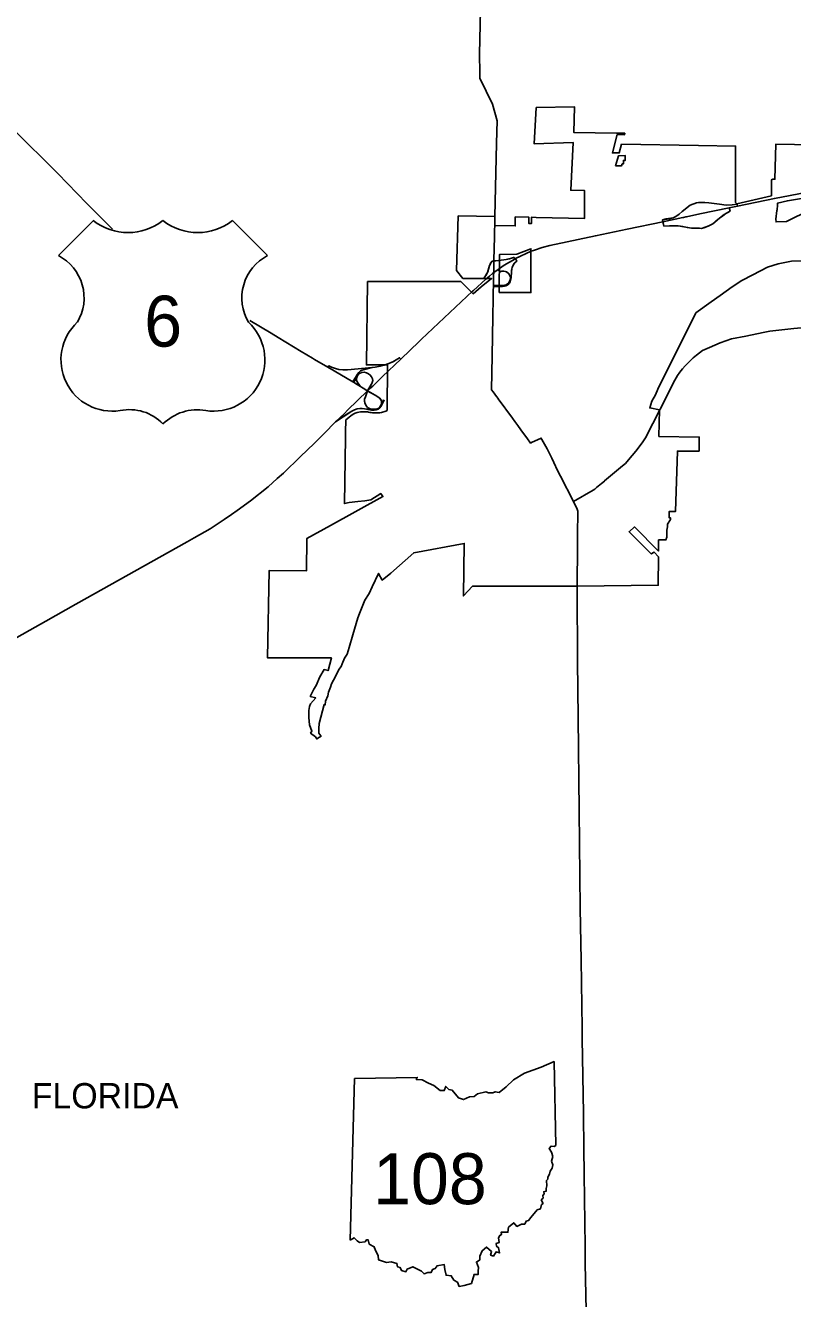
# Model space of a CAD drawing. Extents: x -62 to 810, y 0 to 440.
# Drawn here: x 239.8 to 317.5, y 199.3 to 328.2 of the extents above; entities that cross this region are included whole.
import ezdxf

# ---------------------------------------------------------------- set-up
doc = ezdxf.new("R2010")
doc.units = 0
for name, color, linetype in [('Default', 7, 'Continuous'), ('DV_X_Corp_Line', 7, 'Continuous'), ('GM_X_Corporation_Text', 7, 'Continuous'), ('GM_X_State_Route', 7, 'Continuous'), ('PV_P_Text', 7, 'Continuous')]:
    doc.layers.add(name, color=color, linetype=linetype)

msp = doc.modelspace()

# ---------------------------------------------------------------- linework, layer by layer
at = {"layer": 'Default'}
for points in [[(311.94, 309.96), (311.9, 310.13), (311.4, 310.09), (310.78, 310.06), (310.11, 310.14), (309.04, 310.29), (308.25, 310.33), (307.78, 310.28), (307.16, 310.03), (306.34, 309.41), (306.03, 309.14), (305.69, 308.89), (305.44, 308.76), (304.71, 308.66), (304.36, 308.55)], [(304.36, 308.55), (304.49, 307.92), (305.05, 307.96), (305.94, 307.94), (307.29, 307.73), (308.28, 307.69), (309.03, 307.94), (309.45, 308.17), (310.13, 308.72), (310.6, 309.11), (311.19, 309.43), (311.11, 309.78)], [(286.47, 302.54), (286.3, 302.73), (286.44, 302.93), (286.62, 303.23), (286.83, 303.94), (286.98, 304.24), (287.11, 304.36), (287.46, 304.41), (288, 304.49), (288.51, 304.55), (289.05, 304.67), (289.3, 304.75), (289.39, 304.59)], [(289.47, 304.64), (289.61, 304.39), (289.43, 304.23), (289.26, 304.03), (289.13, 303.74), (289.08, 303.59), (289.04, 303.26), (289.02, 302.72), (288.97, 302.41), (288.93, 302.28), (288.75, 302.04), (288.48, 301.87), (288.13, 301.82), (287.22, 301.82)], [(287.22, 301.92), (288.13, 301.92), (288.52, 301.97), (288.75, 302.14), (288.9, 302.39), (288.94, 302.67), (288.93, 302.81), (288.85, 302.98), (288.78, 303.1), (288.56, 303.28), (288.26, 303.37), (288.09, 303.36), (287.86, 303.29), (287.69, 303.53)], [(270.46, 293.64), (270.55, 293.77), (270.84, 293.63), (271.23, 293.49), (271.57, 293.41), (271.96, 293.36), (272.43, 293.38), (274.94, 293.61), (275.25, 293.64), (275.76, 293.73), (276.17, 293.84), (276.63, 294), (277.11, 294.22), (277.37, 294.37), (277.72, 294.6), (277.86, 294.45)], [(272.99, 292.16), (273.45, 292.94), (273.59, 293.11), (273.78, 293.26), (274.02, 293.37), (274.94, 293.61)], [(273.06, 292.11), (273.48, 292.82), (273.58, 292.95), (273.72, 293.04), (273.91, 293.11), (274.14, 293.12), (274.37, 293.07), (274.56, 292.97), (274.75, 292.84), (274.89, 292.66), (274.98, 292.47), (275, 292.28), (274.96, 292.09), (274.89, 291.93), (274.47, 291.23)], [(273.73, 291.71), (273.42, 292.15), (273.37, 292.31), (273.36, 292.48), (273.41, 292.68), (273.48, 292.82)], [(276.15, 290.33), (276.12, 290.23), (275.81, 289.67), (275.71, 289.53), (275.56, 289.4), (275.35, 289.31), (275.12, 289.27), (274.87, 289.29), (274.53, 289.35), (274.16, 289.42), (273.94, 289.44), (273.69, 289.44), (273.42, 289.41), (273.15, 289.33), (272.87, 289.19), (272.39, 288.87), (271.24, 288.1)], [(275.85, 289.81), (275.72, 289.63), (275.65, 289.55), (275.55, 289.47), (275.44, 289.42), (275.19, 289.37), (274.98, 289.38), (274.75, 289.42), (274.48, 289.57), (274.37, 289.69), (274.29, 289.8), (274.19, 290.04), (274.17, 290.27), (274.18, 290.39), (274.26, 290.65), (274.47, 291.23)], [(274.47, 291.23), (275.24, 290.81), (275.71, 290.49), (275.84, 290.3), (275.88, 290.13), (275.88, 289.96), (275.85, 289.81), (276.07, 290.25), (276.1, 290.34)]]:
    msp.add_lwpolyline(points, dxfattribs=at)
at = {"layer": 'DV_X_Corp_Line'}
for points in [[(318.46, 304.41), (317.4, 304.36), (316.05, 304.12), (314.97, 303.76), (313.49, 303), (312.37, 302.42), (311.4, 301.76), (310.2, 300.9), (309.27, 300.24), (307.72, 299.14), (305.01, 293.72), (304.06, 291.78), (303.89, 291.4), (303.64, 290.85), (303.28, 290.2), (303.05, 289.51), (304.03, 289.33), (303.99, 286.62), (308.07, 286.56), (308.05, 285.15), (305.86, 285.15), (305.65, 279.02), (305.03, 279.03), (305.03, 278.38), (305.17, 278.38), (305.17, 278.23), (304.87, 277.74), (304.86, 277.46), (304.78, 277.13), (304.77, 276.42), (304.69, 276.14), (303.95, 276.14), (303.94, 275.01), (301.5, 277.46), (300.97, 276.98), (303.21, 274.73), (303.49, 274.91), (303.93, 274.44), (303.92, 271.55), (295.7, 271.45), (285.11, 271.46), (284.19, 270.48), (284.27, 275.79), (279.16, 274.84), (276.84, 272.79), (275.96, 272.08), (275.59, 272.75), (274.96, 271.39), (274.65, 270.72), (274.19, 270.03), (273.67, 268.69), (273.48, 268.24), (273, 266.54), (272.6, 265.24), (272.42, 264.56), (272.14, 264.18), (271.89, 263.61), (271.82, 263.33), (271.57, 263.03), (271.23, 262.33), (270.84, 261.58), (270.74, 261.24), (270.52, 260.72), (270.45, 260.35), (270.21, 259.81), (270.19, 259.44), (270.09, 259.47), (269.58, 257.57), (269.53, 257.04), (269.56, 256.59), (269.75, 256.31), (269.77, 256.27), (269.61, 256.17), (269.33, 255.99), (269.19, 256.21), (268.71, 256.59), (268.85, 256.78), (268.59, 257.43), (268.52, 258.15), (268.54, 258.86), (268.6, 259.27), (268.71, 259.56), (269.23, 260.14), (268.68, 260.3), (269.04, 261.04), (269.28, 261.42), (269.64, 262.27), (270.08, 263.02), (270.48, 262.92), (270.81, 264.19), (264.34, 264.21), (264.51, 273.04), (268.31, 273.03), (268.33, 276.29), (270.73, 277.62), (276.03, 280.53), (275.82, 280.84), (274.82, 280.2), (274.2, 280.1), (273.51, 280.04), (272.6, 279.93), (272.14, 279.83), (272.23, 286.47), (272.24, 287.4), (272.28, 287.96), (272.29, 288.22), (272.29, 288.29), (272.41, 288.41), (272.62, 288.58), (272.78, 288.72), (273.01, 288.88), (273.22, 288.97), (273.42, 289.05), (273.76, 289.11), (273.84, 289.12), (274.03, 289.13), (274.22, 289.12), (274.29, 289.11), (274.48, 289.1), (274.57, 289.08), (274.71, 289.06), (274.84, 289.04), (274.99, 289.03), (275.13, 289.01), (275.22, 289.01), (275.33, 289.01), (275.52, 289.01), (275.72, 289.03), (275.9, 289.04), (276.34, 289.19), (276.46, 289.26), (276.49, 293.87), (274.36, 293.87), (274.48, 302.3), (283.92, 302.31), (285.17, 301.07), (285.99, 301.79), (287.03, 302.61), (284.14, 302.62), (283.49, 303.42), (283.67, 308.96), (287.38, 308.88), (287.36, 307.98), (289.44, 307.94), (289.44, 308.85), (290.81, 308.83), (290.8, 308.19), (291.08, 308.18), (291.08, 308.82), (291.57, 308.81), (296.44, 308.69), (296.44, 311.53), (295.05, 311.55), (295.31, 316.39), (291.36, 316.25), (291.56, 319.93), (295.45, 320), (295.36, 317.41), (299.68, 317.33), (300.53, 317.32), (300.5, 317.18), (299.76, 317.19), (299.27, 315.34), (299.97, 315.33), (300.21, 316.22), (307.98, 316.09), (311.75, 316.02), (311.75, 312.41), (311.75, 311.94), (311.75, 310.31), (311.89, 310.18), (315.37, 310.99), (315.37, 311.53), (315.39, 312.62), (315.53, 312.67), (315.73, 312.67), (315.82, 316.22), (323.35, 316.08)], [(319.65, 310.93), (316.99, 310.49), (316.01, 310.26), (316.01, 310.05), (315.97, 309.56), (315.93, 309.49), (315.82, 308.63), (315.85, 308.34), (316.9, 308.39), (321.62, 310.73)]]:
    msp.add_lwpolyline(points, dxfattribs=at)
for points in [[(299.59, 314.02), (300.21, 314.03), (300.27, 314.23), (300.39, 314.23), (300.39, 314.58), (300.58, 314.58), (300.58, 315.06), (299.88, 315.04)], [(287.81, 301.19), (291.03, 301.19), (291.03, 305.63), (289.58, 305.07), (287.83, 305.04)]]:
    msp.add_lwpolyline(points, close=True, dxfattribs=at)
at = {"layer": 'GM_X_State_Route'}
for points in [[(285.82, 325.35), (286.13, 338.85), (286.31, 346.44), (286.48, 354.03), (286.82, 369.18), (287.34, 391.58)], [(198.53, 333.88), (207.22, 331.68), (212.44, 330.67), (218.02, 329.23), (220.04, 328.78), (225.63, 327.52), (227.85, 327.08), (228.67, 326.87), (229.44, 326.61), (229.96, 326.29), (230.45, 325.9), (231.43, 324.88), (234.84, 321.46), (239.2, 317.13), (242.46, 313.89), (243.11, 313.25), (246.06, 310.2), (246.72, 309.53), (248.65, 307.6)], [(285.84, 323.71), (285.84, 323.86), (285.81, 324.92), (285.82, 325.35)], [(287.54, 316.31), (287.59, 318.6), (287.13, 320.26), (285.86, 322.91), (285.84, 323.71)], [(287.41, 310.36), (287.54, 316.31)], [(306.78, 308.87), (308.12, 309.15), (311.11, 309.78), (311.94, 309.96), (315.68, 310.73), (318.86, 311.33), (321.03, 311.55), (323.21, 311.68), (323.38, 311.68)], [(287.38, 308.87), (287.38, 308.88), (287.41, 310.36)], [(308.13, 310.33), (308, 310.33), (307.78, 310.28), (307.16, 310.03), (306.8, 309.78), (306.34, 309.41), (306.03, 309.14), (305.69, 308.89), (305.44, 308.76), (305.06, 308.65), (304.36, 308.55), (304.39, 308.37)], [(311.11, 309.78), (311.19, 309.43), (310.75, 309.21), (310.45, 308.98), (310.13, 308.72), (309.74, 308.42), (309.45, 308.17), (309.03, 307.94), (308.64, 307.79), (308.28, 307.69), (307.29, 307.73), (306.86, 307.79), (306.41, 307.87), (305.94, 307.94), (305.53, 307.96), (305.05, 307.96), (304.49, 307.92), (304.39, 308.37)], [(311.94, 309.96), (311.9, 310.13), (311.4, 310.09), (310.78, 310.06), (310.11, 310.14), (309.58, 310.22), (309.04, 310.29), (308.65, 310.31), (308.25, 310.33), (308.13, 310.33)], [(287.34, 307.38), (287.36, 308.12)], [(287.36, 308.12), (287.38, 308.87)], [(291.3, 305.46), (291.38, 305.49), (292.17, 305.77), (292.95, 305.97), (297.56, 306.94), (300.76, 307.61), (304.39, 308.37), (306.42, 308.8), (306.48, 308.81)], [(304.39, 308.37), (304.49, 307.92), (305.05, 307.96), (305.53, 307.96), (305.94, 307.94), (306.41, 307.87), (306.86, 307.79), (307.29, 307.73), (308.02, 307.7), (308.1, 307.7)], [(306.48, 308.81), (306.72, 308.86), (306.78, 308.87)], [(287.33, 306.78), (287.34, 307.38)], [(287.27, 304.4), (287.3, 305.74)], [(287.3, 305.74), (287.33, 306.78)], [(287.27, 304.4), (287.17, 304.38), (287.11, 304.36), (287.04, 304.3), (286.98, 304.24), (286.93, 304.17), (286.89, 304.08), (286.83, 303.94), (286.73, 303.56), (286.69, 303.38), (286.62, 303.23), (286.54, 303.08), (286.44, 302.93), (286.36, 302.8), (286.3, 302.73), (286.47, 302.54)], [(287.22, 301.82), (287.39, 301.81), (287.79, 301.82), (288.13, 301.82), (288.33, 301.83), (288.48, 301.87), (288.63, 301.95), (288.75, 302.04), (288.86, 302.16), (288.93, 302.28), (288.97, 302.41), (289, 302.55), (289.02, 302.72), (289.04, 303.26), (289.05, 303.42), (289.08, 303.59), (289.13, 303.74), (289.18, 303.89), (289.26, 304.03), (289.34, 304.13), (289.43, 304.23), (289.53, 304.33), (289.61, 304.39), (289.47, 304.64)], [(287.25, 303.22), (287.27, 304.4)], [(289.39, 304.59), (289.3, 304.75), (289.26, 304.73), (289.05, 304.67), (288.84, 304.62), (288.51, 304.55), (287.77, 304.43), (287.46, 304.41), (287.27, 304.4)], [(287.83, 303.63), (288.31, 303.97), (289.39, 304.59), (289.47, 304.64), (291.04, 305.37), (291.3, 305.46)], [(285.12, 301.33), (285.2, 301.4), (286.47, 302.54), (286.84, 302.86), (287.12, 303.11)], [(287.12, 303.11), (287.13, 303.12), (287.25, 303.22)], [(287.69, 303.53), (287.86, 303.29), (287.9, 303.31), (288.09, 303.36), (288.26, 303.37), (288.42, 303.34), (288.56, 303.28), (288.69, 303.2), (288.78, 303.1), (288.85, 302.98), (288.93, 302.81), (288.94, 302.67), (288.94, 302.55), (288.9, 302.39), (288.85, 302.28), (288.75, 302.14), (288.64, 302.05), (288.52, 301.97), (288.38, 301.93), (288.25, 301.91), (288.04, 301.9), (287.41, 301.91), (287.22, 301.92)], [(287.24, 302.9), (287.25, 303.22)], [(287.25, 303.22), (287.69, 303.53), (287.83, 303.63)], [(287.21, 301.36), (287.22, 301.82), (287.22, 301.92), (287.24, 302.9)], [(279.71, 296.25), (279.95, 296.48), (285.12, 301.33)], [(287.2, 300.29), (287.2, 300.32), (287.21, 300.9)], [(287.21, 300.9), (287.21, 300.93), (287.21, 301.36)], [(287.17, 299.07), (287.2, 300.29)], [(262.56, 298.35), (264.7, 297.07), (265.43, 296.63), (267.75, 295.24), (268.91, 294.55), (269, 294.5)], [(287.1, 294.79), (287.17, 298.76)], [(287.17, 298.76), (287.17, 298.79), (287.17, 299.07)], [(315.23, 297.3), (317.65, 297.55), (323.83, 298.09), (328.62, 298.4), (330.19, 298.59)], [(306.64, 293.78), (306.67, 293.81), (307.1, 294.26), (307.44, 294.58), (307.78, 294.86), (308.4, 295.32), (309.1, 295.62), (310.19, 296.12), (311.34, 296.5), (312.77, 296.79)], [(312.77, 296.79), (312.78, 296.79), (314.55, 297.16)], [(314.55, 297.16), (315.23, 297.3)], [(275.99, 292.68), (276, 292.69), (277.86, 294.45), (279.71, 296.25)], [(269, 294.5), (269.12, 294.42), (270.46, 293.64)], [(277.86, 294.45), (277.72, 294.6), (277.37, 294.37), (277.03, 294.19), (276.63, 294), (276.17, 293.84), (275.76, 293.73), (275.25, 293.64), (274.94, 293.61), (274.23, 293.53), (272.43, 293.38), (271.96, 293.36), (271.57, 293.41), (271.23, 293.49), (270.84, 293.63), (270.55, 293.77), (270.46, 293.64)], [(287.71, 290.42), (287.69, 290.45), (287.54, 290.66), (287.19, 291.14), (287.04, 291.34), (287.1, 294.79)], [(270.46, 293.64), (271.11, 293.26), (272.99, 292.16), (273.06, 292.11), (273.42, 291.9), (274.21, 291.4)], [(274.94, 293.61), (274.24, 293.43), (274.02, 293.37), (273.78, 293.26), (273.59, 293.11), (273.45, 292.94), (273.04, 292.25), (272.99, 292.16)], [(273.06, 292.11), (273.12, 292.2), (273.48, 292.82), (273.41, 292.68)], [(273.73, 291.71), (273.5, 292.03), (273.42, 292.15), (273.37, 292.31), (273.36, 292.48), (273.41, 292.68), (273.48, 292.82), (273.58, 292.95), (273.72, 293.04), (273.91, 293.11), (274.14, 293.12), (274.37, 293.07), (274.56, 292.97), (274.75, 292.84), (274.89, 292.66), (274.98, 292.47), (275, 292.28), (274.96, 292.09), (274.89, 291.93), (274.86, 291.88), (274.47, 291.23)], [(274.68, 291.43), (275, 291.73), (275.99, 292.68)], [(304.08, 289.33), (304.1, 289.39), (305.6, 292.32), (305.88, 292.8), (306.09, 293.14), (306.36, 293.48), (306.64, 293.78)], [(274.21, 291.4), (274.34, 291.32)], [(274.58, 291.33), (274.68, 291.43)], [(271.24, 288.1), (272.67, 289.06), (272.87, 289.19), (273.15, 289.33), (273.42, 289.41), (273.69, 289.44), (273.94, 289.44), (274.16, 289.42), (274.43, 289.37), (274.87, 289.29), (275.12, 289.27), (275.35, 289.31), (275.56, 289.4), (275.71, 289.53), (275.81, 289.67), (276.12, 290.23), (276.15, 290.33)], [(272.13, 288.96), (272.46, 289.28), (274.47, 291.23)], [(275.78, 290.41), (275.84, 290.3), (275.88, 290.13), (275.88, 289.96), (275.85, 289.81), (275.72, 289.63), (275.65, 289.55), (275.55, 289.47), (275.44, 289.42), (275.19, 289.37), (274.98, 289.38), (274.75, 289.42), (274.61, 289.49), (274.48, 289.57), (274.37, 289.69), (274.29, 289.8), (274.22, 289.96), (274.19, 290.04), (274.18, 290.15), (274.17, 290.27), (274.18, 290.39), (274.26, 290.65), (274.37, 290.94)], [(274.34, 291.32), (274.47, 291.23), (274.74, 291.08)], [(274.37, 290.94), (274.47, 291.23)], [(274.47, 291.23), (274.58, 291.33)], [(274.74, 291.08), (275.24, 290.81), (275.71, 290.49), (275.77, 290.41), (275.78, 290.41)], [(276.1, 290.34), (276.07, 290.25), (275.91, 289.95), (275.85, 289.81)], [(290.6, 286.48), (290.58, 286.51), (290.01, 287.29), (289.68, 287.74), (289.39, 288.13), (289.14, 288.48), (287.71, 290.42)], [(203.42, 246.07), (217.26, 254.07), (234.38, 263.69), (241.91, 267.93), (244.92, 269.63), (256.21, 275.94), (256.92, 276.34), (258.55, 277.28), (259.95, 278.2), (260.7, 278.72), (261.26, 279.12), (262.61, 280.12), (264.4, 281.53), (265.33, 282.35), (265.96, 282.89), (267.7, 284.59), (269.07, 285.92), (270.07, 286.92), (271.24, 288.1), (272.13, 288.96)], [(298.48, 282.12), (300.3, 283.64), (300.59, 283.88), (300.9, 284.25), (301.66, 285.14), (302.28, 285.99), (302.68, 286.58), (302.7, 286.63), (304.04, 289.25), (304.08, 289.33)], [(291.09, 286), (291.06, 285.99), (290.99, 285.95), (290.6, 286.48)], [(292.14, 286.32), (292.11, 286.36), (292.06, 286.45), (291.09, 286)], [(293.33, 283.98), (293.15, 284.41), (292.68, 285.38), (292.14, 286.32)], [(294.02, 282.61), (293.72, 283.19), (293.33, 283.98)], [(295.33, 280.02), (294.02, 282.61)], [(295.33, 280.02), (297.31, 281.19), (297.48, 281.3), (297.67, 281.45)], [(297.67, 281.45), (298.18, 281.87), (298.47, 282.11), (298.48, 282.12)], [(295.73, 274.48), (295.73, 274.94), (295.73, 275.38), (295.74, 276.09), (295.75, 276.78), (295.75, 277.27), (295.76, 278.42), (295.77, 278.95), (295.76, 279.03), (295.76, 279.05), (295.7, 279.26), (295.33, 280.02)], [(295.7, 271.45), (295.71, 272.54), (295.73, 274.45), (295.73, 274.48)], [(295.7, 271.15), (295.7, 271.45)], [(296.33, 217.94), (296.33, 218.09), (296.22, 225.62), (296.21, 226.7), (296.1, 233.6), (296.02, 238.82), (295.9, 248.75), (295.81, 258.14), (295.74, 263.88), (295.7, 271.15)], [(296.73, 185.88), (296.73, 187.78), (296.61, 198.1), (296.52, 202.86), (296.5, 204.59), (296.42, 211.89), (296.39, 214.54), (296.33, 217.94), (296.33, 217.94)]]:
    msp.add_lwpolyline(points, dxfattribs=at)
at = {"layer": 'PV_P_Text'}
for p, q in [((246.71, 308.48), (243.17, 304.94)), ((264.35, 304.94), (260.8, 308.48)), ((272.7, 205.23), (273.16, 221.6)), ((272.7, 205.23), (273.16, 221.6))]:
    msp.add_line(p, q, dxfattribs=at)
for points in [[(273.16, 221.6), (279.51, 221.71), (279.41, 221.51), (280.01, 221.47), (280.65, 221.12), (281.18, 220.9), (281.84, 220.38), (282.24, 220.38), (282.4, 220.81), (282.71, 220.48), (283.06, 220.42), (283.68, 219.64), (284.19, 219.47), (284.81, 219.74), (285.26, 219.78), (285.6, 220.05), (286.47, 220.27), (286.71, 220.14), (287.17, 220.17), (287.41, 220.27), (287.81, 220.18), (288.52, 220.77), (289.25, 221.47), (290.37, 222.14), (292.05, 222.76), (293.37, 223.32), (293.56, 214.83)], [(273.16, 221.6), (279.51, 221.71), (279.41, 221.51), (280.01, 221.47), (280.65, 221.12), (281.18, 220.9), (281.84, 220.38), (282.24, 220.38), (282.4, 220.81), (282.71, 220.48), (283.06, 220.42), (283.68, 219.64), (284.19, 219.47), (284.81, 219.74), (285.26, 219.78), (285.6, 220.05), (286.47, 220.27), (286.71, 220.14), (287.17, 220.17), (287.41, 220.27), (287.81, 220.18), (288.52, 220.77), (289.25, 221.47), (290.37, 222.14), (292.05, 222.76), (293.37, 223.32), (293.56, 214.83)], [(293.56, 214.83), (293.37, 214.71), (293.06, 214.76), (292.86, 214.53), (293.11, 214.13), (293.23, 213.71), (293.12, 213.25), (293.23, 212.86), (293.16, 212.54), (292.97, 212.23), (292.9, 211.92), (292.74, 211.6), (292.75, 211.42), (292.6, 211.28), (292.62, 210.75), (292.55, 210.46), (292.57, 210.2), (292.32, 210.14), (292.38, 209.93), (292.22, 209.76), (292.25, 209.49), (292.07, 209.31), (292.25, 208.95), (292.11, 208.84), (291.99, 208.4), (291.67, 208.32), (291.02, 207.52), (290.79, 207.22), (290.54, 207.15), (290.4, 206.84), (290.08, 206.84), (289.6, 206.63), (289.29, 206.99), (288.75, 206.55), (288.69, 206.04), (288.01, 206.06), (288.03, 205.8), (287.88, 205.72), (287.74, 205.47), (287.82, 205.01), (287.5, 204.89), (287.54, 204.62), (287.75, 204.46), (287.84, 203.95), (287.5, 204.05), (287.22, 203.62), (286.93, 203.72), (287.03, 204.09), (286.54, 204.53), (286.09, 204.17), (285.85, 203.61), (285.84, 203.24), (285.5, 203.01), (285.72, 202.48), (285.68, 202.11), (285.69, 201.76), (285.26, 201.77), (285, 200.83)], [(293.56, 214.83), (293.37, 214.71), (293.06, 214.76), (292.86, 214.53), (293.11, 214.13), (293.23, 213.71), (293.12, 213.25), (293.23, 212.86), (293.16, 212.54), (292.97, 212.23), (292.9, 211.92), (292.74, 211.6), (292.75, 211.42), (292.6, 211.28), (292.62, 210.75), (292.55, 210.46), (292.57, 210.2), (292.32, 210.14), (292.38, 209.93), (292.22, 209.76), (292.25, 209.49), (292.07, 209.31), (292.25, 208.95), (292.11, 208.84), (291.99, 208.4), (291.67, 208.32), (291.02, 207.52), (290.79, 207.22), (290.54, 207.15), (290.4, 206.84), (290.08, 206.84), (289.6, 206.63), (289.29, 206.99), (288.75, 206.55), (288.69, 206.04), (288.01, 206.06), (288.03, 205.8), (287.88, 205.72), (287.74, 205.47), (287.82, 205.01), (287.5, 204.89), (287.54, 204.62), (287.75, 204.46), (287.84, 203.95), (287.5, 204.05), (287.22, 203.62), (286.93, 203.72), (287.03, 204.09), (286.54, 204.53), (286.09, 204.17), (285.85, 203.61), (285.84, 203.24), (285.5, 203.01), (285.72, 202.48), (285.68, 202.11), (285.69, 201.76), (285.26, 201.77), (285, 200.83)], [(285, 200.83), (284.26, 200.65), (283.75, 200.55), (283.57, 200.97), (283.2, 201.2), (282.96, 201.63), (282.43, 201.69), (282.3, 202.28), (282.25, 202.76), (281.52, 202.64), (281.33, 202.35), (281.07, 202.27), (280.92, 201.97), (280.57, 201.95), (280.2, 201.81), (279.95, 202.1), (279.34, 202.39), (279.06, 202.54), (278.48, 202.31), (278.36, 202.03), (277.9, 202.15), (277.79, 202.46), (277.51, 202.55), (277.45, 202.88), (276.86, 203.05), (276.4, 202.98), (275.6, 203.24), (275.55, 203.67), (275.28, 204.2), (275.14, 204.56), (274.63, 204.84), (274.53, 205.27), (274.37, 205.26), (274.22, 205.08), (273.65, 205), (273.43, 205.18), (273.11, 205.48), (272.7, 205.23)], [(285, 200.83), (284.26, 200.65), (283.75, 200.55), (283.57, 200.97), (283.2, 201.2), (282.96, 201.63), (282.43, 201.69), (282.3, 202.28), (282.25, 202.76), (281.52, 202.64), (281.33, 202.35), (281.07, 202.27), (280.92, 201.97), (280.57, 201.95), (280.2, 201.81), (279.95, 202.1), (279.34, 202.39), (279.06, 202.54), (278.48, 202.31), (278.36, 202.03), (277.9, 202.15), (277.79, 202.46), (277.51, 202.55), (277.45, 202.88), (276.86, 203.05), (276.4, 202.98), (275.6, 203.24), (275.55, 203.67), (275.28, 204.2), (275.14, 204.56), (274.63, 204.84), (274.53, 205.27), (274.37, 205.26), (274.22, 205.08), (273.65, 205), (273.43, 205.18), (273.11, 205.48), (272.7, 205.23)]]:
    msp.add_lwpolyline(points, dxfattribs=at)
for centre, radius, start, end in [((250.23, 312.96), 5.7, 231.813, 308.187), ((257.28, 312.96), 5.7, 231.813, 308.187), ((240.95, 300.66), 4.82, 329.1175, 62.6108), ((266.57, 300.66), 4.82, 117.3892, 210.8825), ((248.63, 294.38), 5.2, 133.0046, 278.7282), ((258.88, 294.38), 5.2, 261.2718, 46.9954), ((250.38, 284.69), 4.65, 43.4177, 101.8742), ((257.23, 284.38), 4.94, 79.9613, 134.7468)]:
    msp.add_arc(centre, radius, start, end, dxfattribs=at)

# ---------------------------------------------------------------- texts
at = {"layer": 'GM_X_Corporation_Text'}
msp.add_text('FLORIDA', height=2.565, rotation=0, dxfattribs=at).set_placement((240.47, 218.58))
at = {"layer": 'PV_P_Text'}
for s, height, p in [('6', 5.16, (251.86, 295.72)), ('108', 5.162, (275.03, 208.88))]:
    msp.add_text(s, height=height, dxfattribs=at).set_placement(p)

doc.saveas('drawing.dxf')
